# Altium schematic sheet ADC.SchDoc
size A4; Organization: ORGANIZATION; Address1: ADDRESS 1; Address2: ADDRESS 2; Address3: ADDRESS 3; Address4: ADDRESS 4; Revision: -; SheetNumber: 4; SheetTotal: 4; ENG_APP_DATE: --/--/--; DSN_APP_DATE: --/--/--; CHK_APP_DATE: --/--/--
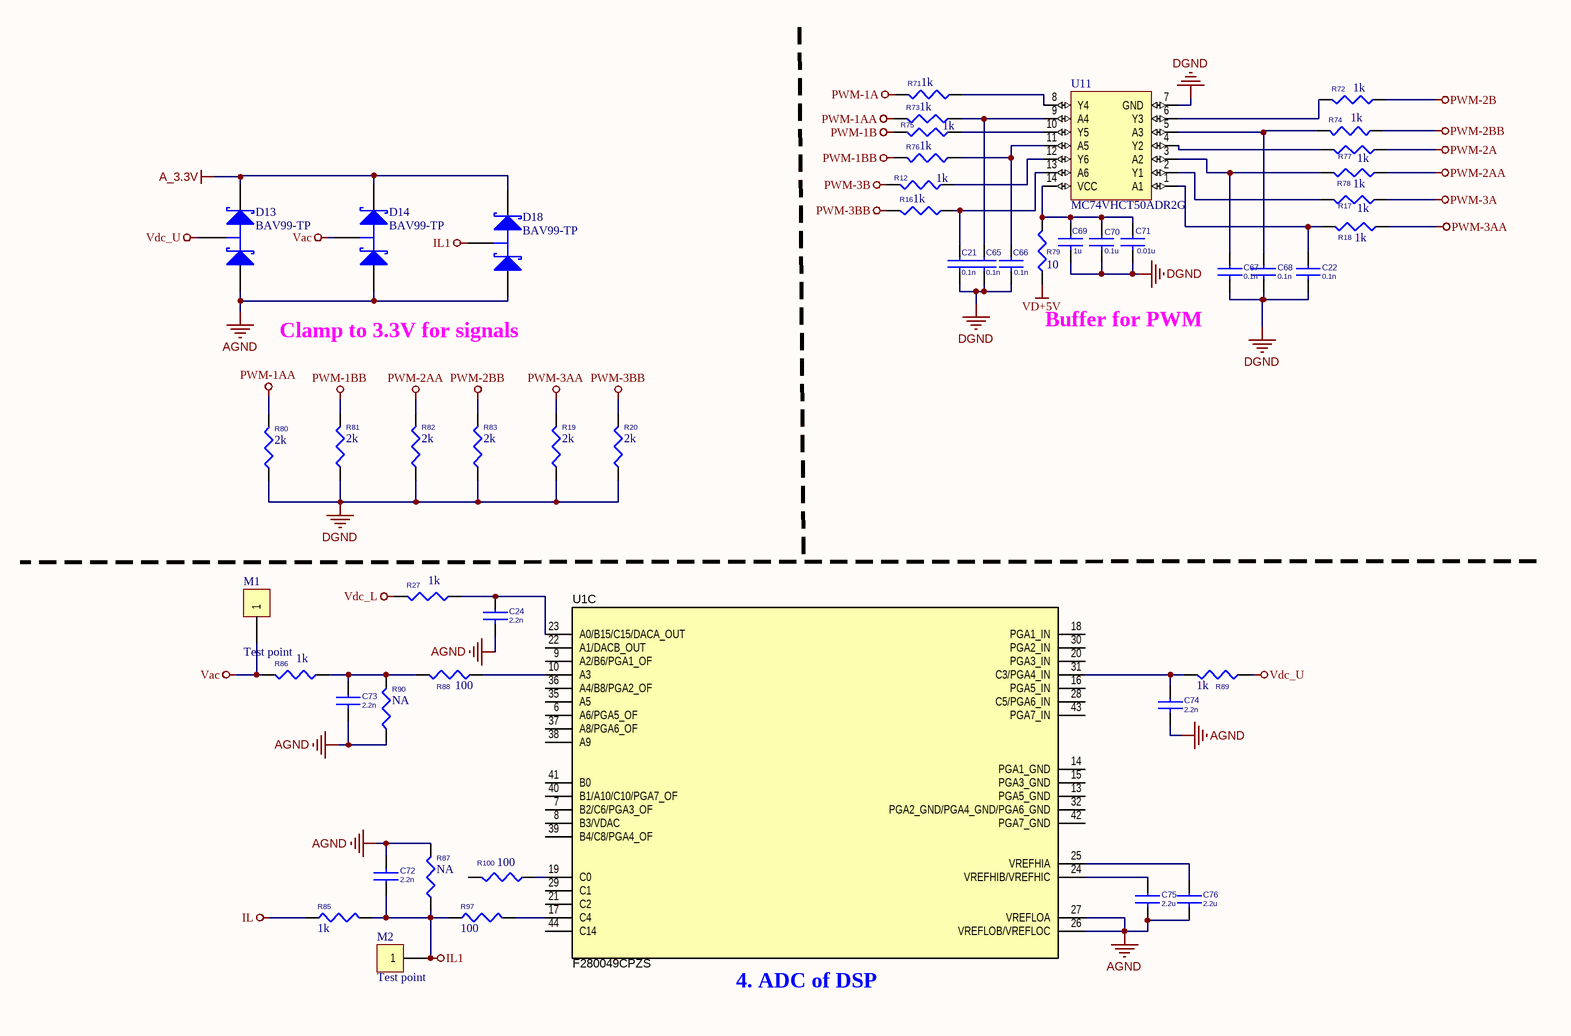
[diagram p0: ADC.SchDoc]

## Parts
C21  0.1n  [C0402]
C22  0.1n  [C0402]
C24  2.2n  [C0402]
C65  0.1n  [C0402]
C66  0.1n  [C0402]
C67  0.1n  [C0402]
C68  0.1n  [C0402]
C69  1u  [C0402]
C70  0.1u  [C0402]
C71  0.01u  [C0402]
C72  2.2n  [C0402]
C73  2.2n  [C0402]
C74  2.2n  [C0402]
C75  2.2u  [C0402]
C76  2.2u  [C0402]
D13  BAV99-TP  [SOT-23-3]
D14  BAV99-TP  [SOT-23-3]
D18  BAV99-TP  [SOT-23-3]
M1  Test point  [1P]
M2  Test point  [1P]
R12  1k  [R0402]
R16  1k  [R0402]
R17  1k  [R0402]
R18  1k  [R0402]
R19  2k  [R0402]
R20  2k  [R0402]
R27  1k  [R0402]
R71  1k  [R0402]
R72  1k  [R0402]
R73  1k  [R0402]
R74  1k  [R0402]
R75  1k  [R0402]
R76  1k  [R0402]
R77  1k  [R0402]
R78  1k  [R0402]
R79  10  [R0402]
R80  2k  [R0402]
R81  2k  [R0402]
R82  2k  [R0402]
R83  2k  [R0402]
R85  1k  [R0402]
R86  1k  [R0402]
R87  NA  [R0402]
R88  100  [R0402]
R89  1k  [R0402]
R90  NA  [R0402]
R97  100  [R0402]
R100  100  [R0402]
U1  F280049CPZS  [PZ0100A_N]  (part C of 5)
U11  MC74VHCT50ADR2G  [14SOIC]

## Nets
A_3.3V: D13.2(K) D14.2(K) D18.2(K)
AGND: C24.2 C72.2 C73.2 C74.2 C75.2 C76.2 D13.1(A) D14.1(A) D18.1(A) R87.1 R90.1 U1.26(VREFLOB/VREFLOC) U1.27(VREFLOA)
DGND: C21.2 C22.2 C65.2 C66.2 C67.2 C68.2 C69.2 C70.2 C71.2 R19.1 R20.1 R80.1 R81.1 R82.1 R83.1 U11.7(GND)
IL: R85.2
IL1: C72.1 D18.3(C) M2.1 R85.1 R87.2 R97.2
PWM-1A: R71.1
PWM-1AA: R73.1 R80.2
PWM-1B: R75.1
PWM-1BB: R76.1 R81.2
PWM-2A: R77.1
PWM-2AA: R78.1 R82.2
PWM-2B: R72.1
PWM-2BB: R74.1 R83.2
PWM-3A: R17.1
PWM-3AA: R18.1 R19.2
PWM-3B: R12.1
PWM-3BB: R16.1 R20.2
Vac: D14.3(C) M1.1 R86.2
VD+5V: R79.1
Vdc_L: R27.2
Vdc_U: D13.3(C) R89.2
NetC21_1: C21.1 R16.2 U11.13(A6)
NetC22_1: C22.1 R18.2 U11.1(A1)
NetC24_1: C24.1 R27.1 U1.23(A0/B15/C15/DACA_OUT)
NetC65_1: C65.1 R73.2 U11.9(A4)
NetC66_1: C66.1 R76.2 U11.11(A5)
NetC67_1: C67.1 R78.2 U11.3(A2)
NetC68_1: C68.1 R74.2 U11.5(A3)
NetC69_1: C69.1 C70.1 C71.1 R79.2 U11.14(VCC)
NetC73_1: C73.1 R86.1 R88.2 R90.2
NetC74_1: C74.1 R89.1 U1.31(C3/PGA4_IN)
NetC75_1: C75.1 U1.24(VREFHIB/VREFHIC)
NetC76_1: C76.1 U1.25(VREFHIA)
NetR12_2: R12.2 U11.12(Y6)
NetR17_2: R17.2 U11.2(Y1)
NetR71_2: R71.2 U11.8(Y4)
NetR72_2: R72.2 U11.6(Y3)
NetR75_2: R75.2 U11.10(Y5)
NetR77_2: R77.2 U11.4(Y2)
NetR88_1: R88.1 U1.10(A3)
NetR97_1: R97.1 U1.17(C4)
NetR100_1: R100.1 U1.19(C0)

Not connected (* = marked no-connect by the designer): R100 2; U1 6(A6/PGA5_OF) 7(B2/C6/PGA3_OF) 8(B3/VDAC) 9(A2/B6/PGA1_OF) 13(PGA5_GND) 14(PGA1_GND) 15(PGA3_GND) 16(PGA5_IN) 18(PGA1_IN) 20(PGA3_IN) 21(C2) 22(A1/DACB_OUT) 28(C5/PGA6_IN) 29(C1) 30(PGA2_IN) 32(PGA2_GND/PGA4_GND/PGA6_GND) 35(A5) 36(A4/B8/PGA2_OF) 37(A8/PGA6_OF) 38(A9) 39(B4/C8/PGA4_OF) 40(B1/A10/C10/PGA7_OF) 41(B0) 42(PGA7_GND) 43(PGA7_IN) 44(C14)

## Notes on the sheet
- Clamp to 3.3V for signals
- Buffer for PWM
- (near U1) 4. ADC of DSP

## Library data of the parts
C21 C22 C65-C68 = CAP NP_Dup1: CAP CER 100PF 25V X7R 0402; PCB Footprint: C1206
C24 C72-C74 = CAP NP_Dup1: CAP CER 2200PF 25V X7R 0402; PCB Footprint: C1206
C69 = CAP NP_Dup1: CAP CER 1UF 25V X5R 0402; PCB Footprint: C1206
C70 = CAP NP_Dup1: CAP CER 0.1UF 25V X7R 0402; PCB Footprint: C1206
C71 = CAP NP_Dup1: CAP CER 0.012UF 25V X7R 0402; PCB Footprint: C1206
C75 C76 = CAP NP_Dup1: CAP CER 2.2UF 25V JB 0402; PCB Footprint: C1206
D13 D14 D18 = CMP-004-00011-1: Schottky Barrier Diode, 70 V, 70 mA, -55 to 125 degC, 3-Pin SOT23, RoHS, Tape and Reel; Manufacturer: Diodes Inc; Manufacturer: Diodes; Manufacturer Part Number: BAS70-04-7-F; Power: 200mW; Peak Reverse Current: 0.1uA; Forward Voltage: 1V; Element Configuration: CommonCathode; Recovery Time: 5ns; Max Surge Current: 1dA; Forward Current: 70mA; Elements: 2
M1 M2 = Test
R12 R16-R18 R27 R71-R78 R85 R86 R89 = RESISTOR_Dup1: RES 1K OHM 1% 1/8W 0402; PCB Footprint: R0603
R19 R20 R80-R83 = RESISTOR_Dup1: RCC0402 100 2K0 1% ET7 E3; PCB Footprint: R0603
R79 = RESISTOR_Dup1: RES 10 OHM 1% 1/8W 0402; PCB Footprint: R0603
R87 R90 = RESISTOR_Dup1: PCB Footprint: R0603
R88 R97 R100 = RESISTOR_Dup1: RES 0.1 OHM 5% 1/8W 0402; PCB Footprint: R0603
U1 = CMP-0078352-1: Piccolo Microcontroller, PZ0100A (LQFP-100); Manufacturer: Texas Instruments; SizeArea_mm2: 256; SizeAreaWB_mm2: 324; SizeX_mm: 16; SizeZ_mm: 1.6; CompType: IC; AEC Category: Q200; AEC Qualified: N
U11 = MC74VHCT50A_SOIC14: IC BUF NON-INVERT 5.5V 14SOIC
